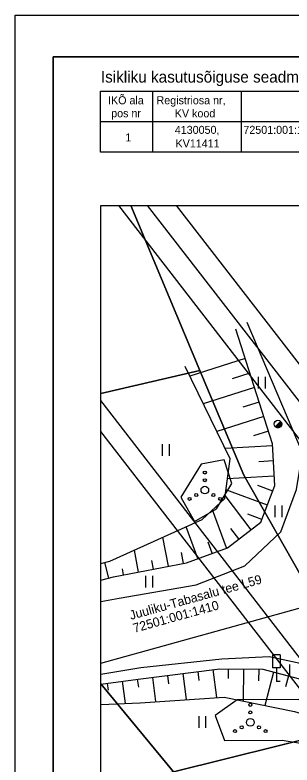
# Model space of a CAD drawing. Extents: x 533279.3 to 533331.8, y 6581483.1 to 6581557.3.
# Drawn here: x 533279.29 to 533297.45, y 6581508.13 to 6581557.32 of the extents above; entities that cross this region are included whole.
import ezdxf

# ---------------------------------------------------------------- set-up
doc = ezdxf.new("R2010")
doc.units = 0
for name, color, linetype in [('HALJASTUS', 7, 'Continuous'), ('LIIKLUS', 7, 'Continuous'), ('PIIR', 7, 'Continuous'), ('POST', 7, 'Continuous'), ('PR_SIDE', 7, 'Continuous'), ('RELJEEF', 7, 'Continuous'), ('RP-nõlv', 7, 'Continuous'), ('RP-tee_servajoon', 7, 'Continuous'), ('RP-telg_tee', 7, 'Continuous'), ('TEE', 7, 'Continuous'), ('VORMISTUS', 7, 'Continuous')]:
    doc.layers.add(name, color=color, linetype=linetype)

msp = doc.modelspace()

# ---------------------------------------------------------------- linework, layer by layer
at = {"layer": 'HALJASTUS'}
for p, q in [((533295.237, 6581533.587), (533295.237, 6581532.826)), ((533295.692, 6581533.587), (533295.692, 6581532.826)), ((533288.939, 6581529.174), (533288.939, 6581528.413)), ((533289.394, 6581529.174), (533289.394, 6581528.413)), ((533296.334, 6581525.141), (533296.334, 6581524.38)), ((533296.789, 6581525.141), (533296.789, 6581524.38)), ((533287.852, 6581520.539), (533287.852, 6581519.777)), ((533288.307, 6581520.539), (533288.307, 6581519.777)), ((533297.284, 6581514.711), (533297.284, 6581513.95)), ((533291.334, 6581511.333), (533291.334, 6581510.572)), ((533291.789, 6581511.333), (533291.789, 6581510.572))]:
    msp.add_line(p, q, dxfattribs=at)
for points in [[(533292.5, 6581524.94), (533293.512, 6581526.593), (533293.016, 6581528.153), (533291.487, 6581527.871), (533290.163, 6581525.701), (533291.07, 6581524.104), (533292.5, 6581524.94)], [(533301.596, 6581509.531), (533301.205, 6581510.943), (533297.872, 6581512.419), (533293.85, 6581512.397), (533292.416, 6581511.385), (533293.032, 6581509.744), (533296.798, 6581509.751), (533300.946, 6581509.084), (533301.596, 6581509.531)]]:
    msp.add_lwpolyline(points, dxfattribs=at)
for centre, radius in [((533291.738, 6581527.309), 0.1), ((533291.738, 6581526.809), 0.1), ((533291.738, 6581526.159), 0.25), ((533291.173, 6581525.834), 0.1), ((533292.303, 6581525.834), 0.1), ((533290.738, 6581525.584), 0.1), ((533292.738, 6581525.584), 0.1), ((533294.721, 6581512.077), 0.1), ((533294.721, 6581511.577), 0.1), ((533294.721, 6581510.927), 0.25), ((533294.156, 6581510.602), 0.1), ((533295.286, 6581510.602), 0.1), ((533293.721, 6581510.352), 0.1), ((533295.721, 6581510.352), 0.1)]:
    msp.add_circle(centre, radius, dxfattribs=at)
at = {"layer": 'LIIKLUS'}
for p, q in [((533296.18, 6581515.347), (533296.18, 6581514.497)), ((533296.68, 6581515.347), (533296.18, 6581515.347)), ((533296.68, 6581515.347), (533296.68, 6581514.497)), ((533296.68, 6581514.497), (533296.18, 6581514.497)), ((533296.43, 6581514.497), (533296.43, 6581513.597)), ((533296.68, 6581513.597), (533296.43, 6581513.597))]:
    msp.add_line(p, q, dxfattribs=at)
at = {"layer": 'PIIR'}
for points in [[(533286.879, 6581544.821), (533291.41, 6581534.01), (533284.919, 6581532.5)], [(533314.039, 6581492.321), (533303.4, 6581511.09), (533294.3, 6581527.13), (533291.41, 6581534.01), (533286.879, 6581544.821)], [(533284.919, 6581532.5), (533291.41, 6581534.01), (533294.3, 6581527.13), (533303.4, 6581511.09), (533289.68, 6581507.68), (533284.919, 6581513.462)], [(533284.919, 6581513.462), (533289.68, 6581507.68), (533284.919, 6581506.535)], [(533301.868, 6581492.321), (533289.68, 6581507.68), (533303.4, 6581511.09), (533314.039, 6581492.321)]]:
    msp.add_lwpolyline(points, dxfattribs=at)
at = {"layer": 'POST'}
msp.add_line((533296.35, 6581530.309), (533296.704, 6581530.663), dxfattribs=at)
msp.add_circle((533296.527, 6581530.486), 0.25, dxfattribs=at)
for radius, start, end in [(0.225, 224.8541, 45.0356), (0.2, 224.8427, 45.047), (0.175, 224.8281, 45.0616), (0.15, 224.8087, 45.081), (0.125, 224.7814, 45.1083), (0.1, 224.7406, 45.1491), (0.075, 224.6725, 45.2172), (0.05, 224.5363, 45.3534), (0.025, 224.1278, 45.7619)]:
    msp.add_arc((533296.527, 6581530.486), radius, start, end, dxfattribs=at)
at = {"layer": 'PR_SIDE'}
msp.add_line((533284.919, 6581514.808), (533320.872, 6581524.815), dxfattribs=at)
at = {"layer": 'RELJEEF'}
for p, q in [((533294.387, 6581534.789), (533290.751, 6581533.629)), ((533294.691, 6581533.837), (533293.526, 6581533.465)), ((533294.995, 6581532.884), (533291.639, 6581531.813)), ((533295.299, 6581531.931), (533294.227, 6581531.589)), ((533295.603, 6581530.979), (533292.526, 6581529.997)), ((533295.907, 6581530.026), (533294.928, 6581529.714)), ((533296.18, 6581529.068), (533293.066, 6581528.892)), ((533296.236, 6581528.069), (533295.277, 6581528.015)), ((533296.292, 6581527.071), (533293.22, 6581526.897)), ((533296.19, 6581526.097), (533295.214, 6581526.466)), ((533295.836, 6581525.161), (533293.123, 6581526.188)), ((533294.766, 6581523.561), (533293.069, 6581525.796)), ((533293.166, 6581522.365), (533292.244, 6581524.862)), ((533295.482, 6581524.226), (533294.554, 6581524.577)), ((533291.29, 6581521.672), (533290.518, 6581523.761)), ((533293.97, 6581522.956), (533293.449, 6581523.642)), ((533289.362, 6581521.166), (533288.994, 6581523.073)), ((533292.228, 6581522.018), (533291.963, 6581522.736)), ((533287.398, 6581520.787), (533287.12, 6581522.228)), ((533290.344, 6581521.355), (533290.206, 6581522.069)), ((533285.438, 6581520.391), (533285.182, 6581521.419)), ((533288.38, 6581520.976), (533288.272, 6581521.534)), ((533286.416, 6581520.597), (533286.339, 6581521)), ((533289.296, 6581514.004), (533289.366, 6581513.453)), ((533290.288, 6581514.13), (533290.506, 6581512.418)), ((533291.28, 6581514.257), (533291.355, 6581513.666)), ((533292.272, 6581514.383), (533292.505, 6581512.552)), ((533293.268, 6581514.435), (533293.262, 6581513.802)), ((533294.268, 6581514.425), (533294.248, 6581512.331)), ((533295.268, 6581514.415), (533295.261, 6581513.652)), ((533296.245, 6581514.228), (533295.676, 6581512.035)), ((533286.321, 6581513.617), (533286.515, 6581512.17)), ((533287.312, 6581513.75), (533287.381, 6581513.239)), ((533288.304, 6581513.877), (533288.507, 6581512.284)), ((533297.213, 6581513.977), (533297.027, 6581513.262)), ((533285.33, 6581513.484), (533285.391, 6581513.031))]:
    msp.add_line(p, q, dxfattribs=at)
for points in [[(533284.919, 6581520.262), (533285.742, 6581520.467), (533290.534, 6581521.392), (533293.214, 6581522.382), (533295.418, 6581524.056), (533296.327, 6581526.46), (533296.172, 6581529.195), (533293.772, 6581536.719)], [(533284.919, 6581521.353), (533285.51, 6581521.501), (533291.561, 6581524.231), (533293.042, 6581525.599), (533293.4, 6581528.208), (533290.443, 6581534.26)], [(533284.919, 6581513.429), (533287.357, 6581513.757), (533292.718, 6581514.44), (533295.532, 6581514.413), (533298.77, 6581513.572), (533302.044, 6581512.29), (533304.781, 6581509.803), (533308.425, 6581504.368), (533311.925, 6581498.098)], [(533284.919, 6581512.096), (533287.494, 6581512.216), (533293.014, 6581512.587), (533297.606, 6581511.635), (533300.228, 6581510.847), (533301.844, 6581507.98), (533304.308, 6581503.346), (533307.513, 6581497.59)]]:
    msp.add_lwpolyline(points, dxfattribs=at)
at = {"layer": 'RP-nõlv'}
msp.add_line((533314.056, 6581492.321), (533284.919, 6581529.994), dxfattribs=at)
at = {"layer": 'RP-tee_servajoon'}
for p, q in [((533326.169, 6581493.006), (533286.093, 6581544.821)), ((533326.169, 6581497.91), (533289.885, 6581544.821)), ((533315.637, 6581492.321), (533284.919, 6581532.037))]:
    msp.add_line(p, q, dxfattribs=at)
at = {"layer": 'RP-telg_tee'}
msp.add_line((533326.169, 6581495.458), (533287.989, 6581544.821), dxfattribs=at)
at = {"layer": 'TEE'}
for points in [[(533284.919, 6581518.853), (533286.115, 6581519.072), (533291.163, 6581519.939), (533294.36, 6581521.188), (533296.727, 6581523.417), (533297.752, 6581526.189), (533298.149, 6581528.6), (533294.521, 6581537.152)], [(533312.852, 6581498.482), (533309.623, 6581504.459), (533306.388, 6581511.03), (533305.005, 6581512.072), (533302.788, 6581513.446), (533299.515, 6581514.457), (533295.949, 6581515.216), (533292.859, 6581515.08), (533287.545, 6581514.499), (533284.919, 6581514.072)]]:
    msp.add_lwpolyline(points, dxfattribs=at)
at = {"layer": 'VORMISTUS'}
for p, q in [((533288.305, 6581552.326), (533288.305, 6581548.326)), ((533294.13, 6581552.326), (533294.13, 6581548.326)), ((533284.905, 6581550.326), (533314.405, 6581550.326))]:
    msp.add_line(p, q, dxfattribs=at)
for points in [[(533279.294, 6581557.321), (533331.794, 6581557.321), (533331.794, 6581483.071), (533279.294, 6581483.071)], [(533281.794, 6581485.821), (533329.294, 6581485.821), (533329.294, 6581554.571), (533281.794, 6581554.571)], [(533281.794, 6581554.571), (533329.294, 6581554.571), (533329.294, 6581485.821), (533281.794, 6581485.821)], [(533284.905, 6581552.326), (533314.405, 6581552.326), (533314.405, 6581548.326), (533284.905, 6581548.326)], [(533326.169, 6581492.321), (533284.919, 6581492.321), (533284.919, 6581544.821), (533326.169, 6581544.821)]]:
    msp.add_lwpolyline(points, close=True, dxfattribs=at)

# ---------------------------------------------------------------- texts
at = {"layer": 'PIIR'}
for s, p in [('Juuliku-Tabasalu tee L59', (533286.89, 6581517.641)), ('72501:001:1410', (533287.125, 6581516.798))]:
    msp.add_text(s, height=0.6, rotation=15.579, dxfattribs=at).set_placement(p)
at = {"layer": 'VORMISTUS'}
for s, height, p in [('Isikliku kasutusõiguse seadmise plaan', 0.75, (533284.921, 6581552.889)), ('IKÕ ala', 0.525, (533285.394, 6581551.467)), ('Registriosa nr,', 0.525, (533288.573, 6581551.467)), ('pos nr', 0.525, (533285.599, 6581550.616)), ('KV kood', 0.525, (533289.77, 6581550.608)), ('4130050,', 0.525, (533289.769, 6581549.526)), ('72501:001:1446; Juuliku-Tabasalu tee L37', 0.525, (533294.266, 6581549.526)), ('1', 0.525, (533286.53, 6581549.026)), ('KV11411', 0.525, (533289.818, 6581548.633))]:
    msp.add_text(s, height=height, dxfattribs=at).set_placement(p)

doc.saveas('drawing.dxf')
